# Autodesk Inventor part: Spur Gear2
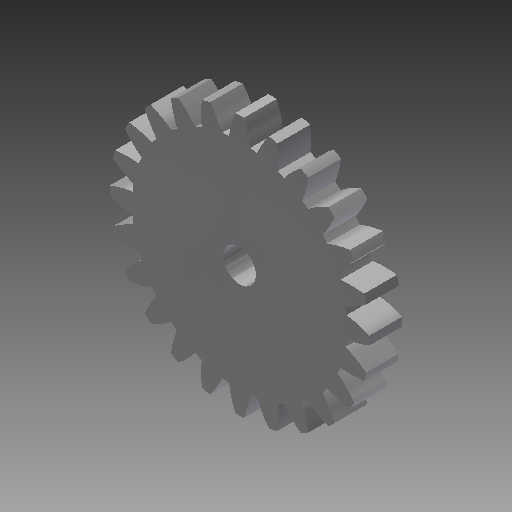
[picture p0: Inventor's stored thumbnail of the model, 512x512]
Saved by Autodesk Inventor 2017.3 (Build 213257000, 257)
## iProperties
Created: 2020-03
Part Number: Spur Gear2
Material: Steel
Document SubType Name: Modeling
Designer: Tim_G
Categories: <?xml version="1.0" encoding="UTF-16"?> <MemberInstance><Categories><FamilyTemplate><FamilyTemplateParameter ValueType="xs:double" Id="1" ObjectReferenceKey="da
Density: 1 g/cm^3
Appearance: Steel
CustomPartVersion: 1
Author: Tim_G
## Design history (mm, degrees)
sketch "Sketch1"
  geometry: C1 r 19.798 at (0, 0)
  constraints: 1 centre point
  dimensions: "d0" = 39.59633 diameter of C1 (= da_da)
extrude "Extrusion1" new body sketch "Sketch1" distance "d1" = 5 (= da_b); taper "d2" = 0 deg
workplane "Work Plane2"
sketch "Sketch2"
  geometry: C1 r 19.798 at (0, 0) reference; C2 r 18.275 at (0, 0)
  constraints: 1 centre point, 1 coincident
  dimensions: "d3" = 36.55046 diameter of C2 (= da_dw)
feature "Pitch Diameter" sketch "Sketch2" dims "d4" = 10, "d5" = 0
workplane "Work Plane8"
workplane "Work Plane9"
feature "Spur Gear" dims "d4" = 10, "da_b" = 5, "da_d" = 36.55046, "da_aw" = 27.41284, "da_da" = 39.59633, "da_df" = 32.74312, "da_dw" = 36.55046, angle "da_beta" = 0 deg, "da_lefttooth" = 0, "da_righttooth" = 0
sketch "Sketch3"
  geometry: C1 r 2.5 at (0, 0); 1 further point
  constraints: 1 centre point, 1 coincident
  dimensions: "d49" = 5 diameter of C1
extrude "Extrusion2" cut sketch "Sketch3" distance "d50" = 5; taper "d51" = 0 deg
body "Solid1"
body "Srf1"
other parameters: "d16" = 27.41284 (= da_aw), "d17" = 0, "d34" = 7.5 deg (computed from da_z), "d39" = 0, "d41" = 0, "d43" = 27.41284 (= da_aw), "d46" = 27.41284 (= da_aw), "d47" = 0, "d48" = 0
